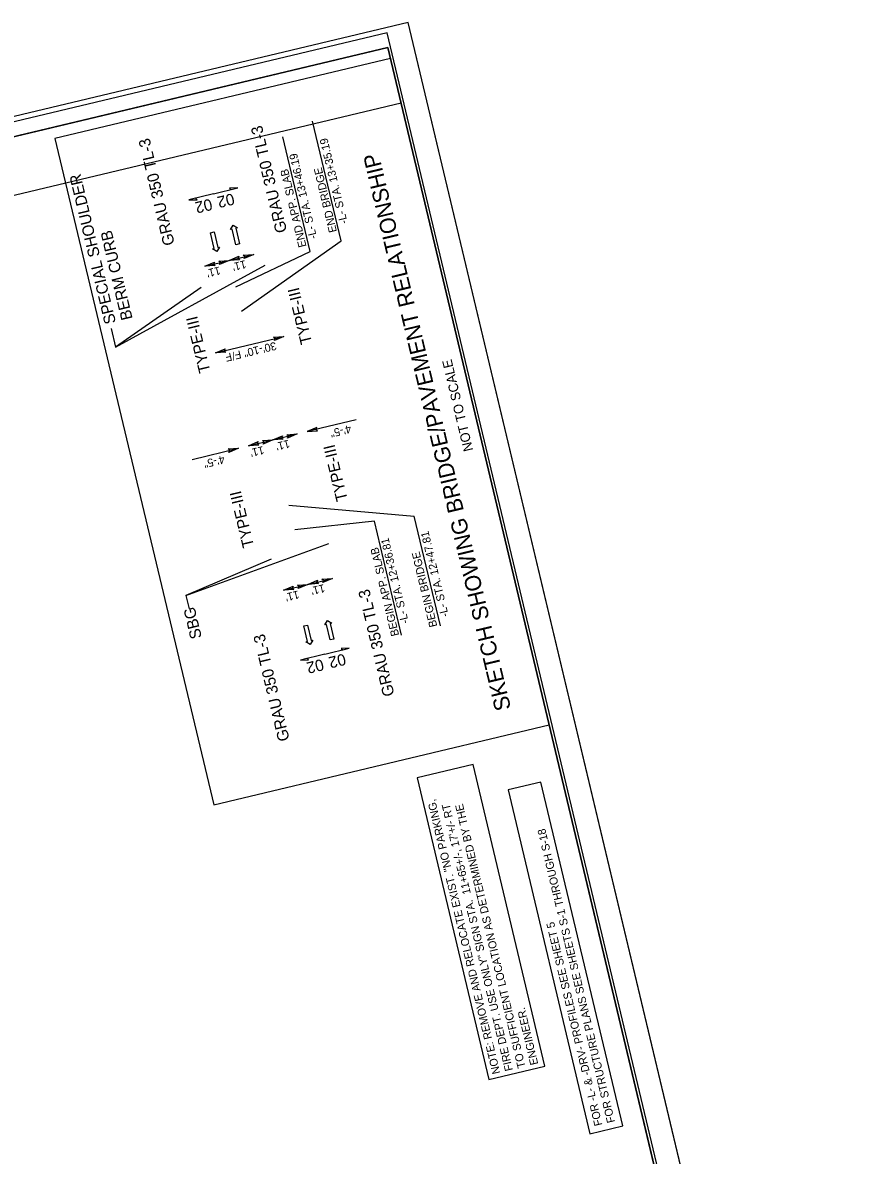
# Model space of a CAD drawing. Extents: x 1735488 to 1736943, y 699358 to 701250.
# Drawn here: x 1736215 to 1736943, y 700259 to 701250 of the extents above; entities that cross this region are included whole.
import ezdxf

# ---------------------------------------------------------------- set-up
doc = ezdxf.new("R2010")
doc.units = 0
for name, color, linetype in [('Default', 7, 'Continuous'), ('Prop Dimension', 7, 'Continuous'), ('Prop Dimension Text', 7, 'Continuous'), ('Prop DSN Text', 7, 'Continuous'), ('Prop Grid Mask', 7, 'Continuous'), ('Prop Guardrail Anchor Unit CELL', 7, 'Continuous'), ('Prop Lane Arrow CELL', 7, 'Continuous'), ('Prop Leader Line Medium', 7, 'Continuous'), ('Prop PFL Text', 7, 'Continuous'), ('Prop Structure Anchor Unit CELL', 7, 'Continuous'), ('Prop Superelevation  Arrow CELL', 7, 'Continuous'), ('Prop Superelevation Label', 7, 'Continuous'), ('Prop Terminator CELL', 7, 'Continuous'), ('Sheet Clip Boundary CELL', 7, 'Continuous'), ('Sheet Cutting Line CELL', 7, 'Continuous'), ('Sheet Layout Plan Border', 7, 'Continuous'), ('Sheet Plan CELL', 7, 'Continuous'), ('Sheet Plan Layout CELL', 7, 'Continuous'), ('Sheet Plot Border Inside CELL', 7, 'Continuous'), ('Sheet Plot Border Outside CELL', 7, 'Continuous')]:
    doc.layers.add(name, color=color, linetype=linetype)

msp = doc.modelspace()

# ---------------------------------------------------------------- linework, layer by layer
at = {"layer": 'Prop Dimension'}
for p, q in [((1736374.8, 701036.8), (1736396.19, 701041.96)), ((1736396.19, 701041.96), (1736417.58, 701047.12)), ((1736296.8, 700966.07), (1736427.58, 701037.67)), ((1736371.62, 701018.14), (1736296.8, 700966.07)), ((1736292.91, 700982.42), (1736296.8, 700966.07)), ((1736384.13, 700960.96), (1736444.08, 700975.43)), ((1736507.19, 700902.52), (1736464.3, 700892.17)), ((1736413.08, 700879.81), (1736434.33, 700884.94)), ((1736434.33, 700884.94), (1736455.71, 700890.11)), ((1736363.73, 700867.9), (1736404.35, 700877.71)), ((1736358.32, 700748.97), (1736483.29, 700794.24)), ((1736432.76, 700780.5), (1736358.32, 700748.97)), ((1736443.66, 700753.45), (1736465.04, 700758.62)), ((1736465.04, 700758.62), (1736486.43, 700763.78)), ((1736358.32, 700748.97), (1736361.12, 700737.21))]:
    msp.add_line(p, q, dxfattribs=at)
at = {"layer": 'Prop Grid Mask'}
for points in [[(1736560.59, 700589.33), (1736623.43, 700325.66), (1736672.31, 700337.31), (1736609.47, 700600.98)], [(1736640.18, 700578.8), (1736711.83, 700278.15), (1736740.54, 700285), (1736668.89, 700585.64)]]:
    msp.add_lwpolyline(points, close=True, dxfattribs=at)
at = {"layer": 'Prop Lane Arrow CELL'}
for p, q in [((1736397.38, 701068.92), (1736399.67, 701072.7)), ((1736399.67, 701072.7), (1736403.51, 701070.38)), ((1736379.76, 701066.03), (1736382.97, 701066.79)), ((1736383.01, 701052.41), (1736379.76, 701066.03)), ((1736382.97, 701066.79), (1736386.22, 701053.17)), ((1736398.84, 701069.27), (1736397.38, 701068.92)), ((1736402.09, 701055.65), (1736398.84, 701069.27)), ((1736403.51, 701070.38), (1736402.05, 701070.03)), ((1736402.05, 701070.03), (1736405.3, 701056.41)), ((1736381.55, 701052.06), (1736383.01, 701052.41)), ((1736385.39, 701049.74), (1736381.55, 701052.06)), ((1736387.67, 701053.52), (1736385.39, 701049.74)), ((1736386.22, 701053.17), (1736387.67, 701053.52)), ((1736405.3, 701056.41), (1736402.09, 701055.65)), ((1736479.75, 700723.23), (1736482.04, 700727.01)), ((1736482.04, 700727.01), (1736485.88, 700724.69)), ((1736485.88, 700724.69), (1736484.42, 700724.34)), ((1736484.42, 700724.34), (1736487.67, 700710.72)), ((1736461.41, 700722.22), (1736464.62, 700722.99)), ((1736464.65, 700708.61), (1736461.41, 700722.22)), ((1736464.62, 700722.99), (1736467.86, 700709.37)), ((1736481.21, 700723.58), (1736479.75, 700723.23)), ((1736484.46, 700709.96), (1736481.21, 700723.58)), ((1736463.19, 700708.26), (1736464.65, 700708.61)), ((1736467.04, 700705.94), (1736463.19, 700708.26)), ((1736469.32, 700709.72), (1736467.04, 700705.94)), ((1736467.86, 700709.37), (1736469.32, 700709.72)), ((1736487.67, 700710.72), (1736484.46, 700709.96))]:
    msp.add_line(p, q, dxfattribs=at)
at = {"layer": 'Prop Leader Line Medium'}
for p, q in [((1736494.11, 701059.12), (1736469.15, 701163.72)), ((1736466.98, 701049.76), (1736443.06, 701150)), ((1736407.01, 700997.43), (1736494.11, 701059.12)), ((1736401.82, 701018.77), (1736466.98, 701049.76)), ((1736558.1, 700817.92), (1736448.27, 700827.53)), ((1736523.2, 700813.85), (1736453.45, 700806.19)), ((1736547, 700714.12), (1736523.2, 700813.85)), ((1736580.94, 700722.23), (1736558.03, 700818.25))]:
    msp.add_line(p, q, dxfattribs=at)
msp.add_lwpolyline([(1736243.69, 701148.53), (1736382.57, 700565.82), (1736676.05, 700635.77), (1736537.17, 701218.48)], close=True, dxfattribs=at)
at = {"layer": 'Prop Superelevation  Arrow CELL'}
for p, q in [((1736382.33, 701100.09), (1736403.71, 701105.26)), ((1736382.33, 701100.09), (1736360.94, 701094.93)), ((1736479.85, 700697.53), (1736458.46, 700692.37)), ((1736479.85, 700697.53), (1736501.23, 700702.7))]:
    msp.add_line(p, q, dxfattribs=at)
for points in [[(1736403.71, 701105.26), (1736396.53, 701105.17), (1736397.98, 701103.87)], [(1736360.94, 701094.93), (1736368.12, 701095.02), (1736366.68, 701096.32)], [(1736501.23, 700702.7), (1736494.05, 700702.61), (1736495.5, 700701.31)], [(1736458.46, 700692.37), (1736465.64, 700692.46), (1736464.2, 700693.75)]]:
    msp.add_lwpolyline(points, close=True, dxfattribs=at)
at = {"layer": 'Prop Terminator CELL'}
for points in [[(1736387.08, 701041.36), (1736396.19, 701041.96), (1736387.77, 701038.28), (1736388.51, 701040.11)], [(1736405.3, 701042.57), (1736396.19, 701041.96), (1736404.61, 701045.64), (1736403.87, 701043.82)], [(1736408.46, 701046.52), (1736417.58, 701047.12), (1736409.15, 701043.45), (1736409.9, 701045.27)], [(1736383.92, 701037.4), (1736374.8, 701036.8), (1736383.23, 701040.48), (1736382.48, 701038.65)], [(1736434.97, 700974.83), (1736444.08, 700975.43), (1736435.66, 700971.75), (1736436.4, 700973.58)], [(1736393.25, 700961.57), (1736384.13, 700960.96), (1736392.55, 700964.64), (1736391.81, 700962.81)], [(1736472.69, 700895.79), (1736464.3, 700892.17), (1736473.47, 700892.74), (1736471.98, 700894.02)], [(1736422.19, 700880.42), (1736413.08, 700879.81), (1736421.5, 700883.49), (1736420.76, 700881.67)], [(1736425.21, 700884.34), (1736434.33, 700884.94), (1736425.91, 700881.26), (1736426.65, 700883.09)], [(1736443.44, 700885.55), (1736434.33, 700884.94), (1736442.75, 700888.62), (1736442.01, 700886.8)], [(1736446.6, 700889.5), (1736455.71, 700890.11), (1736447.29, 700886.43), (1736448.03, 700888.25)], [(1736395.24, 700877.1), (1736404.35, 700877.71), (1736395.93, 700874.03), (1736396.68, 700875.85)], [(1736452.77, 700754.06), (1736443.66, 700753.45), (1736452.08, 700757.13), (1736451.34, 700755.31)], [(1736455.93, 700758.01), (1736465.04, 700758.62), (1736456.62, 700754.94), (1736457.36, 700756.76)], [(1736474.15, 700759.22), (1736465.04, 700758.62), (1736473.46, 700762.3), (1736472.72, 700760.47)], [(1736477.32, 700763.18), (1736486.43, 700763.78), (1736478.01, 700760.1), (1736478.75, 700761.93)]]:
    msp.add_lwpolyline(points, close=True, dxfattribs=at)
at = {"layer": 'Sheet Clip Boundary CELL'}
msp.add_lwpolyline([(1736871.06, 699817.6), (1736546.47, 701179.46), (1735730.8, 700985.06), (1735774.68, 700800.95), (1735568.96, 700751.92), (1735849.67, 699574.16)], close=True, dxfattribs=at)
at = {"layer": 'Sheet Cutting Line CELL'}
msp.add_line((1736943.15, 699612.23), (1736552.83, 701249.86), dxfattribs=at)
at = {"layer": 'Sheet Layout Plan Border'}
msp.add_lwpolyline([(1736871.06, 699817.6), (1736546.47, 701179.46), (1735730.8, 700985.06), (1735774.68, 700800.95), (1735568.96, 700751.92), (1735849.67, 699574.16)], close=True, dxfattribs=at)
at = {"layer": 'Sheet Plan CELL'}
for points in [[(1735513.48, 700984.69), (1735861.26, 699525.52), (1736882.65, 699768.96), (1736534.88, 701228.1)], [(1736882.65, 699768.96), (1735861.29, 699525.5), (1735559.86, 700790.06), (1735705.83, 700824.86), (1735659.46, 701019.45), (1736534.88, 701228.1)]]:
    msp.add_lwpolyline(points, close=True, dxfattribs=at)
at = {"layer": 'Sheet Plan Layout CELL'}
msp.add_lwpolyline([(1735861.29, 699525.5), (1736882.65, 699768.96), (1736534.88, 701228.09), (1735719.21, 701033.68), (1735774.68, 700800.95), (1735568.96, 700751.92)], close=True, dxfattribs=at)
at = {"layer": 'Sheet Plot Border Inside CELL'}
msp.add_lwpolyline([(1736920.68, 699620.24), (1736534.41, 701240.83), (1735508.17, 700996.24), (1735894.43, 699375.64)], close=True, dxfattribs=at)
at = {"layer": 'Sheet Plot Border Outside CELL'}
msp.add_lwpolyline([(1736943.15, 699612.23), (1736552.83, 701249.86), (1735487.67, 700995.98), (1735877.99, 699358.36)], close=True, dxfattribs=at)

# ---------------------------------------------------------------- texts
at = {"layer": 'Default'}
for s, p in [('SPECIAL SHOULDER', (1736297.14, 700987.53)), ('BERM CURB', (1736311.73, 700991.01)), ('SBG', (1736372.28, 700712.16))]:
    msp.add_text(s, height=10, rotation=103.4195, dxfattribs=at).set_placement(p)
at = {"layer": 'Prop Dimension Text'}
for s, rotation, p in [("11'", 193.57439, (1736410.12, 701042.2)), ("11'", 193.57439, (1736387.59, 701036.63)), ('30\'-10" F/F', 193.57439, (1736436.49, 700970.76)), ('4\'-5"', 193.56291, (1736502.07, 700898.16)), ("11'", 193.57439, (1736448.26, 700885.19)), ("11'", 193.57439, (1736425.73, 700879.61)), ('4\'-5"', 193.57439, (1736391.35, 700871.45)), ("11'", 193.57439, (1736478.97, 700758.86)), ("11'", 193.57439, (1736456.45, 700753.28))]:
    msp.add_text(s, height=7, rotation=rotation, dxfattribs=at).set_placement(p)
at = {"layer": 'Prop DSN Text'}
for s, height, rotation, p in [('-L- STA. 13+35.19', 7, 103.41949, (1736499.79, 701074.76)), ('-L- STA. 13+46.19', 7, 103.41949, (1736473.11, 701061.46)), ('SKETCH SHOWING BRIDGE/PAVEMENT RELATIONSHIP', 14, 103.40592, (1736642.84, 700649.95)), ('END APP. SLAB', 7, 103.41949, (1736463.8, 701054.24)), ('END BRIDGE', 7, 103.41949, (1736490.42, 701067.17)), ('NOT TO SCALE', 8.4, 103.40592, (1736609.68, 700875.96)), ('-L- STA. 12+47.81', 7, 103.41949, (1736588.22, 700731.04)), ('-L- STA. 12+36.81', 7, 103.41949, (1736553.29, 700725.14)), ('BEGIN APP. SLAB', 7, 103.41949, (1736544.88, 700714.17)), ('BEGIN BRIDGE', 7, 103.41949, (1736578.28, 700722.04))]:
    msp.add_text(s, height=height, rotation=rotation, dxfattribs=at).set_placement(p)
at = {"layer": 'Prop Guardrail Anchor Unit CELL'}
for p in [(1736446.89, 701067.3), (1736348.56, 701056.22), (1736540.85, 700661.9), (1736449.06, 700622.67)]:
    msp.add_text('GRAU 350 TL-3', height=10, rotation=103.40592, dxfattribs=at).set_placement(p)
at = {"layer": 'Prop PFL Text'}
for s, p in [('NOTE: REMOVE AND RELOCATE EXIST. "NO PARKING,', (1736633.4, 700331.19)), ('TO SUFFICIENT LOCATION AS DETERMINED BY THE', (1736655.53, 700336.46)), ('FIRE DEPT. USE ONLY" SIGN STA.  11+65+/-, 17\'+/- RT', (1736644.47, 700333.82)), ('FOR STRUCTURE PLANS SEE SHEETS S-1 THROUGH S-18', (1736733.81, 700288.5)), ('FOR -L- & -DRV- PROFILES SEE SHEET 5', (1736722.75, 700285.86)), ('ENGINEER.', (1736666.6, 700339.1))]:
    msp.add_text(s, height=7, rotation=103.40592, dxfattribs=at).set_placement(p)
at = {"layer": 'Prop Structure Anchor Unit CELL'}
for p in [(1736468.71, 700969.9), (1736379.78, 700944.84), (1736499.92, 700832.57), (1736417.98, 700792.02)]:
    msp.add_text('TYPE-III', height=10, rotation=103.51075, dxfattribs=at).set_placement(p)
at = {"layer": 'Prop Superelevation Label'}
for p in [(1736379.95, 701096.07), (1736399.33, 701100.78), (1736496.84, 700698.21), (1736477.47, 700693.51)]:
    msp.add_text('02', height=10, rotation=193.57439, dxfattribs=at).set_placement(p)

doc.saveas('drawing.dxf')
